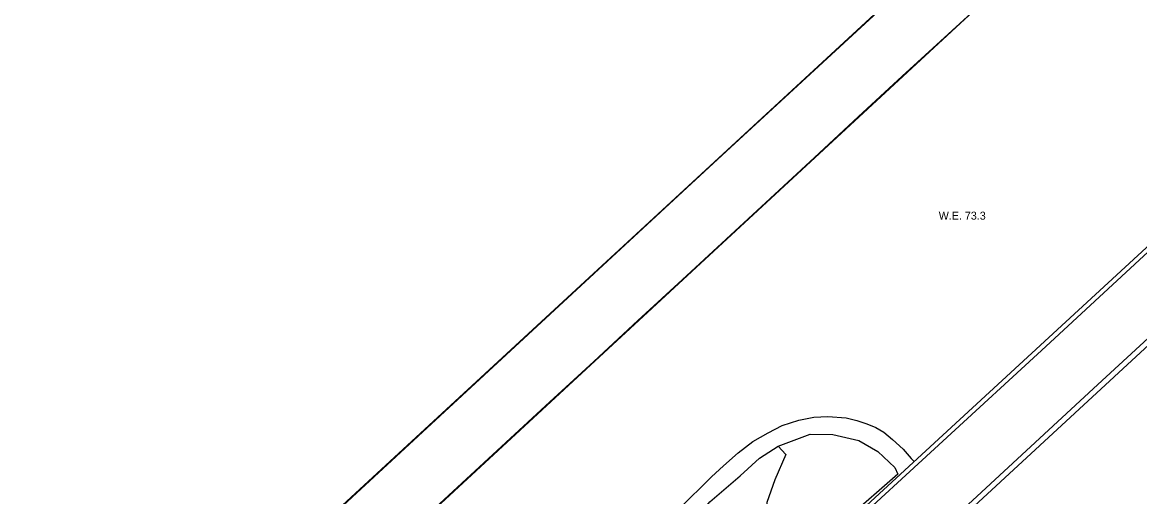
# Model space of a CAD drawing. Extents: x 2161152 to 2175754, y 602179 to 617749.
# Drawn here: x 2171388 to 2171946, y 613438 to 613675 of the extents above; entities that cross this region are included whole.
import ezdxf

# ---------------------------------------------------------------- set-up
doc = ezdxf.new("R2010")
doc.units = 0
for name, color, linetype in [('RD_EX_Bridge', 7, 'Continuous'), ('RD_EX_Conc_Sidewalk', 7, 'Continuous'), ('RD_EX_GuardRail', 7, 'Continuous'), ('RD_EX_H2O', 7, 'Continuous'), ('RD_EX_H2O_txCode', 7, 'Continuous'), ('RD_EX_VEG', 7, 'Continuous')]:
    doc.layers.add(name, color=color, linetype=linetype)

msp = doc.modelspace()

# ---------------------------------------------------------------- linework, layer by layer
at = {"layer": 'RD_EX_Bridge'}
for points in [[(2171389.53, 613284.24), (2171399.38, 613273.52), (2171407.54, 613264.64), (2171410.03, 613261.69), (2172004.16, 613810.97), (2172001.92, 613813.43), (2171992.82, 613823.37), (2171984.61, 613832.35), (2171982.29, 613834.88), (2171387.83, 613286.09), (2171389.53, 613284.24), (2171387.83, 613286.09), (2171982.29, 613834.88), (2171984.61, 613832.35), (2171992.82, 613823.37), (2172001.92, 613813.43), (2172004.16, 613810.97), (2171410.03, 613261.69), (2171407.54, 613264.64), (2171399.38, 613273.52), (2171389.53, 613284.24)], [(2172059.85, 613663.94), (2171794.99, 613419.86), (2171796.4, 613418.3), (2171797.03, 613417.61), (2171799.23, 613415.22), (2171807.08, 613406.69), (2171815.53, 613397.55), (2171817.89, 613395.01), (2171818.14, 613394.74), (2171818.98, 613393.86), (2171819.91, 613392.88), (2172084.33, 613637.18)], [(2172084.33, 613637.18), (2171819.91, 613392.88), (2171818.98, 613393.86), (2171818.14, 613394.74), (2171817.89, 613395.01), (2171815.53, 613397.55), (2171807.08, 613406.69), (2171799.23, 613415.22), (2171797.03, 613417.61), (2171796.4, 613418.3), (2171794.99, 613419.86), (2172059.85, 613663.94)]]:
    msp.add_lwpolyline(points, dxfattribs=at)
at = {"layer": 'RD_EX_Conc_Sidewalk'}
for points in [[(2171828, 613691.94), (2171783.84, 613651.22), (2171739.88, 613610.66), (2171717.81, 613590.29), (2171695.79, 613569.94), (2171673.67, 613549.56), (2171651.74, 613529.23), (2171629.65, 613508.85), (2171607.69, 613488.52), (2171585.61, 613468.27), (2171563.63, 613447.89), (2171541.62, 613427.56)], [(2171541.62, 613427.56), (2171563.63, 613447.89), (2171585.61, 613468.27), (2171607.69, 613488.52), (2171629.65, 613508.85), (2171651.74, 613529.23), (2171673.67, 613549.56), (2171695.79, 613569.94), (2171717.81, 613590.29), (2171739.88, 613610.66), (2171783.84, 613651.22), (2171828, 613691.94)], [(2171871.78, 613688.75), (2171827.59, 613648.14), (2171805.57, 613627.77), (2171783.73, 613607.45), (2171761.64, 613587.09), (2171739.57, 613566.69), (2171717.58, 613546.31), (2171695.56, 613525.99), (2171673.53, 613505.6), (2171651.48, 613485.35), (2171629.56, 613464.97), (2171607.47, 613444.62), (2171585.43, 613424.28)], [(2171585.43, 613424.28), (2171607.47, 613444.62), (2171629.56, 613464.97), (2171651.48, 613485.35), (2171673.53, 613505.6), (2171695.56, 613525.99), (2171717.58, 613546.31), (2171739.57, 613566.69), (2171761.64, 613587.09), (2171783.73, 613607.45), (2171805.57, 613627.77), (2171827.59, 613648.14), (2171871.78, 613688.75)], [(2171871.78, 613688.75), (2171827.59, 613648.14), (2171805.57, 613627.77), (2171783.73, 613607.45), (2171761.64, 613587.09), (2171739.57, 613566.69), (2171717.58, 613546.31), (2171695.56, 613525.99), (2171673.53, 613505.6), (2171651.48, 613485.35), (2171629.56, 613464.97), (2171607.47, 613444.62), (2171585.43, 613424.28)], [(2171585.43, 613424.28), (2171607.47, 613444.62), (2171629.56, 613464.97), (2171651.48, 613485.35), (2171673.53, 613505.6), (2171695.56, 613525.99), (2171717.58, 613546.31), (2171739.57, 613566.69), (2171761.64, 613587.09), (2171783.73, 613607.45), (2171805.57, 613627.77), (2171827.59, 613648.14), (2171871.78, 613688.75)]]:
    msp.add_lwpolyline(points, dxfattribs=at)
at = {"layer": 'RD_EX_GuardRail'}
for points in [[(2171899.49, 613512.96), (2171981.77, 613589.13), (2172061.23, 613662.42), (2171981.77, 613589.13), (2171899.49, 613512.96)], [(2172082.76, 613638.9), (2171925.39, 613494), (2171818.14, 613394.74), (2171925.39, 613494), (2172082.76, 613638.9)], [(2171796.4, 613418.3), (2171899.49, 613512.96), (2171796.4, 613418.3), (2171782.88, 613406.43), (2171749.67, 613382.21), (2171734.3, 613369.72), (2171720.68, 613357.96), (2171666.08, 613307.22), (2171605.89, 613251.61), (2171542.52, 613193.06), (2171490.87, 613145.17), (2171434.83, 613094)]]:
    msp.add_lwpolyline(points, dxfattribs=at)
at = {"layer": 'RD_EX_H2O'}
msp.add_lwpolyline([(2171716.22, 613431.95), (2171732.38, 613447.83), (2171738.39, 613453.36), (2171745.58, 613459.85), (2171753.06, 613465.58), (2171760.62, 613469.86), (2171767.69, 613473.55), (2171775.91, 613476.13), (2171783.5, 613477.75), (2171790.42, 613477.99), (2171799.71, 613477.34), (2171805.04, 613475.98), (2171809.96, 613474.38), (2171814.47, 613472.53), (2171818.5, 613470.24), (2171822.74, 613466.6), (2171828.12, 613461.72), (2171832.12, 613457.1), (2171833.63, 613455.46)], dxfattribs=at)
at = {"layer": 'RD_EX_VEG'}
for points in [[(2171765.67, 613463.21), (2171781.6, 613469.19), (2171793.03, 613468.98), (2171805.93, 613466.05), (2171815.54, 613460.6), (2171823.98, 613452.54), (2171825.44, 613449.28), (2171800.36, 613427.24)], [(2171745.65, 613405.59), (2171736.81, 613409.67), (2171722.1, 613406.83), (2171709.68, 613401.51), (2171701.11, 613399.75), (2171703.22, 613405.77), (2171711.74, 613412.58), (2171722.6, 613424.61), (2171731.55, 613435.4), (2171746.71, 613448.32), (2171756.39, 613457.22), (2171765.67, 613463.21), (2171769.49, 613459.07), (2171763.91, 613446.29), (2171759.99, 613435.04), (2171759.4, 613427.38), (2171760.49, 613421.77), (2171758.51, 613412.32), (2171745.65, 613405.59)]]:
    msp.add_lwpolyline(points, dxfattribs=at)

# ---------------------------------------------------------------- texts
at = {"layer": 'RD_EX_H2O_txCode'}
msp.add_text('W.E. 73.3', height=4, dxfattribs=at).set_placement((2171845.9, 613576.43))

doc.saveas('drawing.dxf')
